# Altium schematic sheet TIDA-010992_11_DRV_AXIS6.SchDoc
size 431 x 279 mm; Date: Not shown in title block; ApprovedBy: Not shown in title block; CheckedBy: Not shown in title block; Author: Not shown in title block; CompanyName: Not shown in title block; Engineer: Not shown in title block; Organization: Not shown in title block; Address1: Not shown in title block; Address2: Not shown in title block; Address3: Not shown in title block; Address4: Not shown in title block; DocumentNumber: 11; Revision: Use project parameter SCH_Rev; SheetNumber: 11; SheetTotal: 13; PageSetup: Record=PageOptions¦CenterHorizontal=True¦CenterVertical=True¦PrintScale=1.00¦XCorrection=1.00¦YCorrection=1.00¦PrintKind=0¦BorderSize=5000000¦LeftOffset=0¦BottomOffset=0¦Orientation=2¦PaperLength=1000¦PaperWidth=1000¦Scale=100¦PaperSource=15¦PrintQuality=600¦MediaType=1¦DitherType=10¦PaperKind=Letter¦PrintScaleMode=1
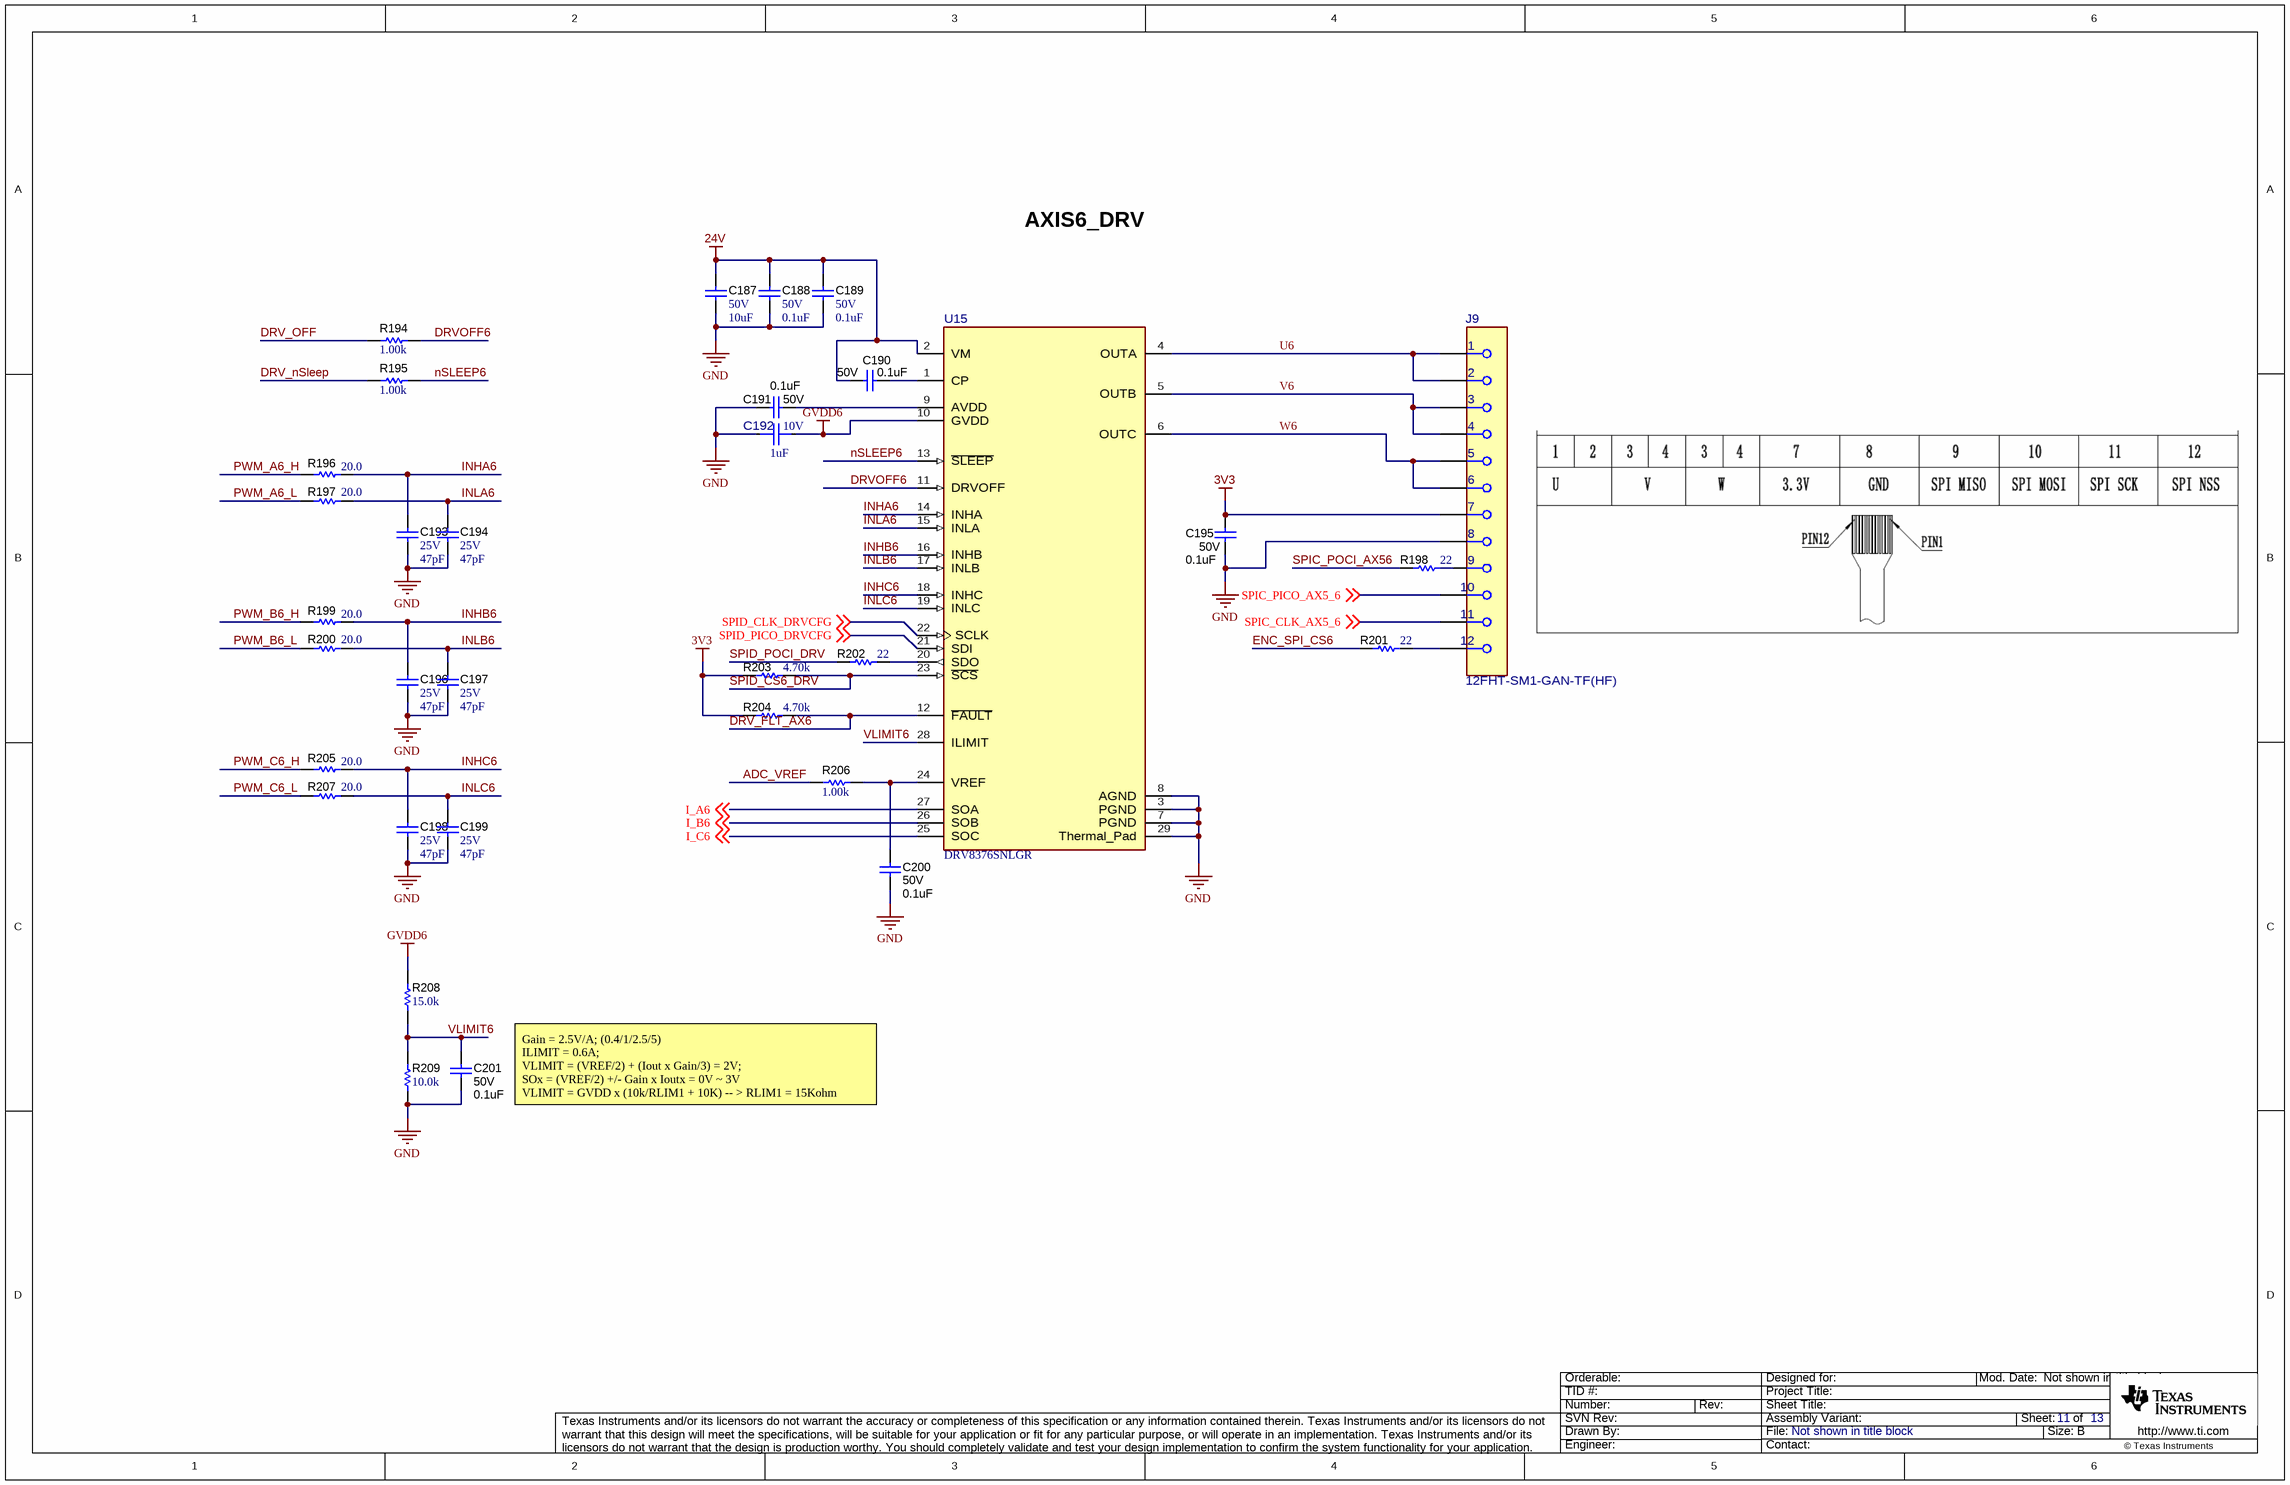
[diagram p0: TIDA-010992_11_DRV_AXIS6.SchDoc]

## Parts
C187  VDC_V: 50V  ValueDisplayed: 10uF  [1206_180]  (hidden comment: CL31B106KBHNNNE)
C188  VDC_V: 50V  ValueDisplayed: 0.1uF  [0402]  (hidden comment: C1005X7R1H104K050BE)
C189  VDC_V: 50V  ValueDisplayed: 0.1uF  [0402]  (hidden comment: C1005X7R1H104K050BE)
C190  VDC_V: 50V  ValueDisplayed: 0.1uF  [0402]  (hidden comment: CGA2B3X7R1H104M050BB)
C191  VDC_V: 50V  ValueDisplayed: 0.1uF  [0402]  (hidden comment: CGA2B3X7R1H104M050BB)
C192  VDC_V: 10V  ValueDisplayed: 1uF  [FP-GMC04X7R105K10NT_0402-MFG]  (hidden comment: GMC04X7R105K10NT)
C193  VDC_V: 25V  ValueDisplayed: 47pF  [0201_033]  (hidden comment: GRM0335C1E470JA01D)
C194  VDC_V: 25V  ValueDisplayed: 47pF  [0201_033]  (hidden comment: GRM0335C1E470JA01D)
C195  VDC_V: 50V  ValueDisplayed: 0.1uF  [0402]  (hidden comment: CGA2B3X7R1H104M050BB)
C196  VDC_V: 25V  ValueDisplayed: 47pF  [0201_033]  (hidden comment: GRM0335C1E470JA01D)
C197  VDC_V: 25V  ValueDisplayed: 47pF  [0201_033]  (hidden comment: GRM0335C1E470JA01D)
C198  VDC_V: 25V  ValueDisplayed: 47pF  [0201_033]  (hidden comment: GRM0335C1E470JA01D)
C199  VDC_V: 25V  ValueDisplayed: 47pF  [0201_033]  (hidden comment: GRM0335C1E470JA01D)
C200  VDC_V: 50V  ValueDisplayed: 0.1uF  [0402]  (hidden comment: CGA2B3X7R1H104M050BB)
C201  VDC_V: 50V  ValueDisplayed: 0.1uF  [0402]  (hidden comment: CGA2B3X7R1H104M050BB)
J9  12FHT-SM1-GAN-TF(HF)  [FP-12FHT-SM1-GAN-TF(HF)_CONN_FPC_12-MFG]
R194  ValueDisplayed: 1.00k  [0402]  (hidden comment: CRCW04021K00FKED)
R195  ValueDisplayed: 1.00k  [0402]  (hidden comment: CRCW04021K00FKED)
R196  ValueDisplayed: 20.0  [0201_033]  (hidden comment: CRCW020120R0FNED)
R197  ValueDisplayed: 20.0  [0201_033]  (hidden comment: CRCW020120R0FNED)
R198  ValueDisplayed: 22  [0201]  (hidden comment: ERJ-1GNJ220C)
R199  ValueDisplayed: 20.0  [0201_033]  (hidden comment: CRCW020120R0FNED)
R200  ValueDisplayed: 20.0  [0201_033]  (hidden comment: CRCW020120R0FNED)
R201  ValueDisplayed: 22  [0201]  (hidden comment: ERJ-1GNJ220C)
R202  ValueDisplayed: 22  [0201]  (hidden comment: ERJ-1GNJ220C)
R203  ValueDisplayed: 4.70k  [0201]  (hidden comment: RC0201FR-7D4K7L)
R204  ValueDisplayed: 4.70k  [0201]  (hidden comment: RC0201FR-7D4K7L)
R205  ValueDisplayed: 20.0  [0201_033]  (hidden comment: CRCW020120R0FNED)
R206  ValueDisplayed: 1.00k  [0402]  (hidden comment: CRCW04021K00FKED)
R207  ValueDisplayed: 20.0  [0201_033]  (hidden comment: CRCW020120R0FNED)
R208  ValueDisplayed: 15.0k  [0402]  (hidden comment: RC0402FR-0715KL)
R209  ValueDisplayed: 10.0k  [0402L]  (hidden comment: CRCW040210K0FKED)
U15  DRV8376SNLGR  [NLG0028A-MFG]

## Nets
3V3: C195.2 J9.7 R203.2 R204.2
24V: C187.1 C188.1 C189.1 C190.1 U15.2(VM)
GND: C187.2 C188.2 C189.2 C191.1 C192.1 C193.2 C194.2 C195.1 C196.2 C197.2 C198.2 C199.2 C200.1 C201.1 J9.8 R209.1 U15.3(PGND) U15.7(PGND) U15.8(AGND) U15.29(Thermal_Pad)
GVDD6: C192.2 R208.2 U15.10(GVDD)
ADC_VREF: R206.1
DRV_FLT_AX6: R204.1 U15.12(~{FAULT})
DRV_nSleep: R195.1
DRV_OFF: R194.1
DRVOFF6: R194.2 U15.11(DRVOFF)
ENC_SPI_CS6: R201.1
I_A6: U15.27(SOA) ; off-sheet I_A6
I_B6: U15.26(SOB) ; off-sheet I_B6
I_C6: U15.25(SOC) ; off-sheet I_C6
INHA6: C193.1 R196.2 U15.14(INHA)
INHB6: C196.1 R199.2 U15.16(INHB)
INHC6: C198.1 R205.2 U15.18(INHC)
INLA6: C194.1 R197.2 U15.15(INLA)
INLB6: C197.1 R200.2 U15.17(INLB)
INLC6: C199.1 R207.2 U15.19(INLC)
nSLEEP6: R195.2 U15.13(~{SLEEP})
PWM_A6_H: R196.1
PWM_A6_L: R197.1
PWM_B6_H: R199.1
PWM_B6_L: R200.1
PWM_C6_H: R205.1
PWM_C6_L: R207.1
SPIC_CLK_AX5_6: J9.11 ; off-sheet SPIC_CLK_AX5_6
SPIC_PICO_AX5_6: J9.10 ; off-sheet SPIC_PICO_AX5_6
SPIC_POCI_AX56: R198.1
SPID_CLK_DRVCFG: U15.22(SCLK) ; off-sheet SPID_CLK_DRVCFG
SPID_CS6_DRV: R203.1 U15.23(~{SCS})
SPID_PICO_DRVCFG: U15.21(SDI) ; off-sheet SPID_PICO_DRVCFG
SPID_POCI_DRV: R202.1
U6: J9.1 J9.2 U15.4(OUTA)
V6: J9.3 J9.4 U15.5(OUTB)
VLIMIT6: C201.2 R208.1 R209.2 U15.28(ILIMIT)
W6: J9.5 J9.6 U15.6(OUTC)
NetC190_2: C190.2 U15.1(CP)
NetC191_2: C191.2 U15.9(AVDD)
NetC200_2: C200.2 R206.2 U15.24(VREF)
NetJ9_9: J9.9 R198.2
NetJ9_12: J9.12 R201.2
NetR202_2: R202.2 U15.20(SDO)

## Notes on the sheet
- AXIS6_DRV
- Gain = 2.5V/A; (0.4/1/2.5/5)
  ILIMIT = 0.6A;
  VLIMIT = (VREF/2) + (Iout x Gain/3) = 2V;
  SOx = (VREF/2) +/- Gain x Ioutx = 0V ~ 3V
  VLIMIT = GVDD x (10k/RLIM1 + 10K) -- > RLIM1 = 15Kohm

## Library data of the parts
C187 = CMP-0008802-2: CAP, CERM, 10 uF, 50 V, +/- 10%, X7R, 1206; Manufacturer: Samsung; TaMin_C: -55°C; Polarized: N; SizeAreaWB_mm2: 10.92; Value1: Unknown; U/M: EA; Value: 10uF; TaMax_C: 125°C; SizeZ_mm: 1.8; SizeX_mm: 3.2; SizeY_mm: 1.6; Cap_Case: 1206; SizeArea_mm2: 5.12; Cap_F: 10µF; AEC Category: Q200
C188 C189 = CMP-0064946-2: CAP, CERM, 0.1 uF, 50 V,+/- 10%, X7R, 0402; Manufacturer: TDK; TaMin_C: -55°C; Polarized: N; SizeAreaWB_mm2: 3; Value1: Unknown; U/M: EA; Value: 0.1uF; TaMax_C: 125°C; SizeZ_mm: 0.6; SizeX_mm: 1; SizeY_mm: 0.5; Cap_F: 100nF; AEC Category: Q200
C190 C191 C195 C200 C201 = CMP-0006326-2: CAP, CERM, 0.1 uF, 50 V, +/- 20%, X7R, AEC-Q200 Grade 1, 0402; Manufacturer: TDK; TaMin_C: -55°C; Polarized: N; SizeAreaWB_mm2: 3; Value1: Unknown; U/M: EA; Value: 0.1uF; TaMax_C: 125°C; SizeZ_mm: 0.6; SizeX_mm: 1; SizeY_mm: 0.5; AEC Qualified: Y; Cap_F: 100nF; AEC Category: Q200
C192 = CMP-0093200-1: 1µF ±10% 10V Ceramic Capacitor X7R 0402 (1005 Metric); Manufacturer: Cal-Chip Electronics; TempCo: 15%; SizeZ_mm: 0.6mm; AEC Qualified: No
C193 C194 C196-C199 = CMP-0009662-3: CAP, CERM, 47 pF, 25 V, +/- 5%, C0G/NP0, 0201; Manufacturer: MuRata; TaMin_C: -55°C; Polarized: N; SizeAreaWB_mm2: 2.08; Value1: Unknown; U/M: EA; Value: 47pF; TaMax_C: 125°C; SizeZ_mm: 0.33; SizeX_mm: 0.6; SizeY_mm: 0.3; Cap_Case: 0201; SizeArea_mm2: 0.18; AEC Category: Q200
J9 = CMP-0126588-1: Conn FPC Connector F 12 POS 0.5mm Solder Ver SMD T/R; Manufacturer: JST; ContactFinish: Gold,Nickel; Current_A: 500mA; Voltage_V: 50V; AEC Qualified: No; Conn Gender: Female; Conn Orientation: Vertical; Is Female: yes; SizeZ_mm: 3.3mm; Standoff Height: 0.13mm
R194 R195 R206 = CMP-0026071-3: RES, 1.00 k, 1%, 0.063 W, AEC-Q200 Grade 0, 0402; Manufacturer: Vishay-Dale; Power_W: 63mW; TempCo: 100 ppm/C; Value_Code: 1k00; Value: 1.00k; EIA_Code: E96; Res_ohm: 1k; SizeX_mm: 1; SizeY_mm: 0.5; SizeZ_mm: 0.6; Value2: 0.063W; AEC Qualified: Y; VDC_V: 50V; AEC Category: Q200; AEC Grade: 0
R196 R197 R199 R200 R205 R207 = CMP-0078192-1: RES, 20.0, 1%, 0.05 W, 0201; Manufacturer: Vishay-Dale; Value_Code: 20R0; SizeArea_mm2: 0.18; AEC Qualified: N; AEC Category: Q200; Res_ohm: 20; Value: 20.0; SizeZ_mm: 0.33; EIA_Code: E96; TempCo: 200 ppm/C; Power_W: 50mW; VDC_V: 30V; SizeY_mm: 0.3; Value2: 0.05W; U/M: EA; SizeX_mm: 0.6
R198 R201 R202 = CMP-0027015-3: RES, 22, 5%, 0.05 W, AEC-Q200 Grade 1, 0201; Manufacturer: Panasonic; Power_W: 50mW; TempCo: 200 ppm/C; Value_Code: 22R0; U/M: EA; Value: 22; EIA_Code: E24; SizeX_mm: 0.6; SizeY_mm: 0.3; SizeZ_mm: 0.26; Value2: 0.05W; SizeArea_mm2: 0.18; AEC Qualified: Y; AEC Grade: 1; AEC Category: Q200
R203 R204 = CMP-0028031-1: RES, 4.70 k, 1%, 0.05 W, 0201; Manufacturer: Yageo America; Power_W: 50mW; TempCo: 200 ppm/C; Value_Code: 4k70; U/M: EA; Value: 4.70k; Res_ohm: 4.7k; SizeX_mm: 0.6; SizeY_mm: 0.3; SizeZ_mm: 0.26; Value2: 0.05W; SizeArea_mm2: 0.18; AEC Qualified: N; VDC_V: 25V; AEC Category: Q200
R208 = CMP-0078583-1: RES, 15.0 k, 1%, 0.063 W, 0402; Manufacturer: Yageo America; Power_W: 63mW; Green_Lifecycle: Active; TempCo: 100 ppm/C; Value_Code: 15k0; Green_REACh: Passed; Value: 15.0k; EIA_Code: E96; Res_ohm: 15k; SizeX_mm: 1; SizeY_mm: 0.5; SizeZ_mm: 0.6; Value2: 0.063W; AEC Qualified: N; AEC Category: Q200
R209 = CMP-0025958-3: RES, 10.0 k, 1%, 0.063 W, AEC-Q200 Grade 0, 0402; Manufacturer: Vishay-Dale; Power_W: 63mW; TempCo: 100 ppm/C; Value_Code: 10k0; Value: 10.0k; EIA_Code: E96; Res_ohm: 10k; SizeX_mm: 1; SizeY_mm: 0.5; SizeZ_mm: 0.6; Value2: 0.063W; AEC Qualified: Y; VDC_V: 50V; AEC Category: Q200; AEC Grade: 0
U15 = CMP-0122073-1: Three-Phase Integrated FET Motor Driver; Manufacturer: Texas Instruments; SizeZ_mm: 1mm; AEC Qualified: No; Max Supply Voltage: 65V; Min Supply Voltage: 4.5V; Motor Type: Brushless DC; Nominal Supply Current: 6.6-8.2mA; Number Of Outputs: 3; Standoff Height: 0mm; Switching Frequency: 100kHz; TaMax_C: +125°C; TaMin_C: -40°C; TJmax_C: +150°C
